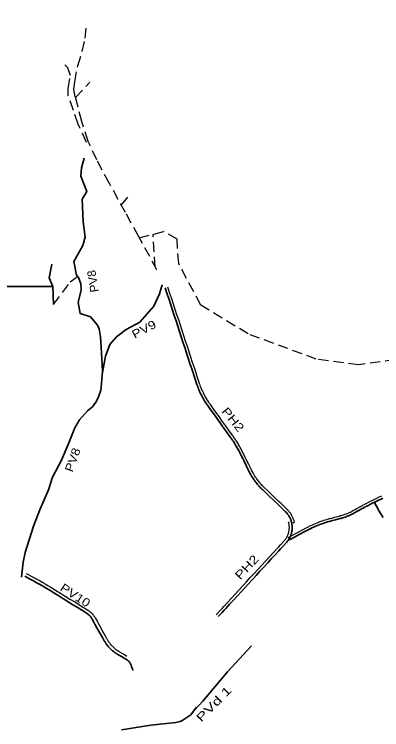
# Model space of a CAD drawing. Extents: x -509392 to -507242, y -1124532 to -1120864.
# Drawn here: x -508657 to -508000, y -1123245 to -1121966 of the extents above; entities that cross this region are included whole.
import ezdxf
from ezdxf.enums import TextEntityAlignment as Align

# ---------------------------------------------------------------- set-up
doc = ezdxf.new("R2010")
doc.units = 0
doc.header["$LTSCALE"] = 6
for name, pattern in [('DOT_DASHED', [7.7, 5, -1.2, 0.3, -1.2]), ('LONG_DASHED', [7.5, 6, -1.5]), ('MEDIUM_DASHED', [4.5, 3, -1.5])]:
    doc.linetypes.add(name, pattern=pattern)
for name, color, linetype, lineweight in [('1', 7, 'DOT_DASHED', 25), ('15', 7, 'Continuous', 35), ('3', 7, 'MEDIUM_DASHED', 25)]:
    doc.layers.add(name, color=color, linetype=linetype, lineweight=lineweight)

msp = doc.modelspace()

# ---------------------------------------------------------------- linework, layer by layer
at = {"layer": '1', "linetype": 'LONG_DASHED'}
msp.add_line((-508477.92, -1123099.313), (-508477.971, -1123099.269), dxfattribs=at)
at = {"layer": '1'}
for points in [[(-508359.897, -1122522.221), (-508363.016, -1122512.72), (-508366.136, -1122503.219), (-508369.255, -1122493.718), (-508372.375, -1122484.217), (-508375.494, -1122474.716), (-508378.614, -1122465.215), (-508381.733, -1122455.714), (-508382.374, -1122453.763)], [(-508251.282, -1122743.872), (-508251.491, -1122743.476), (-508252.955, -1122740.762), (-508254.464, -1122738.065), (-508256.009, -1122735.395), (-508256.289, -1122734.924), (-508257.602, -1122732.739), (-508259.23, -1122730.114), (-508260.896, -1122727.516), (-508261.606, -1122726.434), (-508261.733, -1122726.242), (-508262.607, -1122724.933), (-508264.349, -1122722.389), (-508265.204, -1122721.171), (-508266.132, -1122719.867), (-508267.555, -1122717.886), (-508272.261, -1122711.335), (-508273.389, -1122709.765), (-508276.89, -1122704.892), (-508279.223, -1122701.643), (-508280.39, -1122700.019), (-508281.685, -1122698.216), (-508285.058, -1122693.521), (-508290.892, -1122685.4), (-508296.726, -1122677.278), (-508302.56, -1122669.156), (-508306.271, -1122663.99), (-508307.699, -1122661.967), (-508308.288, -1122661.11), (-508309.079, -1122659.938), (-508310.431, -1122657.876), (-508311.747, -1122655.794), (-508313.029, -1122653.686), (-508313.465, -1122652.95), (-508314.269, -1122651.568), (-508315.478, -1122649.419), (-508316.652, -1122647.249), (-508317.232, -1122646.141), (-508317.784, -1122645.065), (-508318.088, -1122644.463), (-508318.879, -1122642.865), (-508319.939, -1122640.639), (-508320.96, -1122638.398), (-508321.946, -1122636.135), (-508322.135, -1122635.689), (-508322.887, -1122633.868), (-508323.794, -1122631.577), (-508324.66, -1122629.272), (-508325.49, -1122626.945), (-508325.588, -1122626.663), (-508326.278, -1122624.612), (-508328.702, -1122617.231), (-508329.311, -1122615.377), (-508331.821, -1122607.732), (-508331.95, -1122607.337), (-508334.941, -1122598.229), (-508338.061, -1122588.728), (-508341.18, -1122579.227), (-508342.922, -1122573.921), (-508344.299, -1122569.726), (-508347.419, -1122560.225), (-508350.538, -1122550.724), (-508353.658, -1122541.223), (-508356.777, -1122531.722), (-508359.897, -1122522.221)], [(-508158.398, -1122875.663), (-508156.25, -1122874.327), (-508156.894, -1122871.889), (-508156.912, -1122871.822), (-508157.299, -1122870.509), (-508157.744, -1122869.156), (-508158.232, -1122867.817), (-508158.762, -1122866.495), (-508159.333, -1122865.189), (-508159.946, -1122863.903), (-508160.599, -1122862.637), (-508161.23, -1122861.499), (-508161.296, -1122861.383), (-508162.023, -1122860.168), (-508162.794, -1122858.97), (-508163.601, -1122857.796), (-508164.446, -1122856.648), (-508165.326, -1122855.528), (-508166.242, -1122854.436), (-508167.189, -1122853.376), (-508167.989, -1122852.531), (-508168.183, -1122852.332), (-508169.178, -1122851.353), (-508175.342, -1122845.468), (-508178.824, -1122842.143), (-508180.074, -1122840.949), (-508182.574, -1122838.561), (-508189.807, -1122831.655), (-508197.04, -1122824.75), (-508204.272, -1122817.845), (-508209.364, -1122812.982), (-508210.901, -1122811.489), (-508211.389, -1122811.002), (-508212.391, -1122809.984), (-508213.862, -1122808.443), (-508215.305, -1122806.875), (-508216.106, -1122805.979), (-508216.711, -1122805.29), (-508217.872, -1122803.935), (-508218.089, -1122803.676), (-508219.445, -1122802.027), (-508220.766, -1122800.359), (-508222.055, -1122798.668), (-508223.316, -1122796.948), (-508223.733, -1122796.366), (-508224.537, -1122795.217), (-508225.732, -1122793.454), (-508226.893, -1122791.672), (-508228.021, -1122789.867), (-508228.953, -1122788.32), (-508229.112, -1122788.05), (-508230.175, -1122786.201), (-508231.201, -1122784.337), (-508232.193, -1122782.456), (-508233.153, -1122780.548), (-508233.493, -1122779.857), (-508234.92, -1122776.955), (-508237.907, -1122770.882), (-508242.32, -1122761.909), (-508244.042, -1122758.408), (-508246.734, -1122752.936), (-508248.68, -1122748.98), (-508250.06, -1122746.227), (-508250.696, -1122744.993), (-508251.277, -1122743.88)], [(-508167.313, -1122901.536), (-508158.485, -1122896.838), (-508149.658, -1122892.14), (-508140.83, -1122887.442), (-508135.151, -1122884.421), (-508132.447, -1122883.007), (-508131.909, -1122882.732), (-508130.431, -1122881.988), (-508129.699, -1122881.624), (-508126.946, -1122880.289), (-508124.172, -1122878.994), (-508122.677, -1122878.317), (-508121.369, -1122877.737), (-508118.559, -1122876.525), (-508115.727, -1122875.355), (-508113.237, -1122874.367), (-508112.867, -1122874.225), (-508110.009, -1122873.142), (-508107.127, -1122872.101), (-508104.234, -1122871.104), (-508103.601, -1122870.892), (-508101.315, -1122870.146), (-508098.39, -1122869.236), (-508095.454, -1122868.369), (-508093.815, -1122867.906), (-508092.495, -1122867.544), (-508089.541, -1122866.768), (-508084.038, -1122865.365), (-508083.723, -1122865.284), (-508075.915, -1122863.295), (-508075.003, -1122863.063), (-508074.382, -1122862.902), (-508073.045, -1122862.541), (-508072.547, -1122862.402), (-508071.115, -1122861.983), (-508069.186, -1122861.381), (-508067.273, -1122860.74), (-508065.369, -1122860.056), (-508065.312, -1122860.034), (-508063.491, -1122859.336), (-508061.623, -1122858.574), (-508059.772, -1122857.773), (-508057.935, -1122856.931), (-508056.548, -1122856.265), (-508056.129, -1122856.058), (-508054.324, -1122855.136), (-508052.538, -1122854.176), (-508047.942, -1122851.643), (-508044.665, -1122849.837), (-508039.185, -1122846.818), (-508037.43, -1122845.85), (-508035.377, -1122844.718), (-508033.169, -1122843.508), (-508031.069, -1122842.372), (-508030.361, -1122841.991), (-508026.732, -1122840.064), (-508022.38, -1122837.801), (-508021.419, -1122837.308), (-508017.997, -1122835.577), (-508013.602, -1122833.399), (-508012.384, -1122832.805), (-508009.177, -1122831.26), (-508004.74, -1122829.169), (-508003.261, -1122828.484), (-508000.281, -1122827.12)], [(-508295.881, -1123039.702), (-508289.116, -1123032.338), (-508285.549, -1123028.455), (-508282.35, -1123024.974), (-508275.585, -1123017.61), (-508268.82, -1123010.246), (-508262.054, -1123002.882), (-508261.562, -1123002.346), (-508255.289, -1122995.518), (-508248.524, -1122988.153), (-508241.758, -1122980.789), (-508234.993, -1122973.425), (-508228.228, -1122966.061), (-508221.462, -1122958.697), (-508214.697, -1122951.333), (-508207.932, -1122943.969), (-508207.546, -1122943.549), (-508201.166, -1122936.605), (-508194.401, -1122929.241), (-508187.636, -1122921.877), (-508184.672, -1122918.651), (-508180.87, -1122914.512), (-508174.496, -1122907.574), (-508174.157, -1122907.199), (-508173.757, -1122906.745), (-508173.044, -1122905.889), (-508172.36, -1122905.015), (-508171.705, -1122904.121), (-508171.079, -1122903.208), (-508170.482, -1122902.275), (-508169.916, -1122901.322), (-508169.373, -1122900.342), (-508169.203, -1122900.019), (-508168.875, -1122899.372), (-508168.398, -1122898.365), (-508167.956, -1122897.349), (-508167.546, -1122896.319), (-508167.169, -1122895.277), (-508166.825, -1122894.223), (-508166.514, -1122893.156), (-508166.291, -1122892.304), (-508166.239, -1122892.087), (-508166.179, -1122891.834), (-508165.996, -1122891.008), (-508165.787, -1122889.917), (-508165.614, -1122888.822), (-508165.475, -1122887.723), (-508165.371, -1122886.619), (-508165.302, -1122885.513), (-508165.268, -1122884.406), (-508165.27, -1122883.285), (-508165.272, -1122883.158), (-508165.306, -1122882.192), (-508165.377, -1122881.084), (-508165.484, -1122879.981), (-508165.625, -1122878.881), (-508165.801, -1122877.787), (-508166.011, -1122876.699), (-508166.495, -1122874.562), (-508165.43, -1122873.409)]]:
    msp.add_lwpolyline(points, dxfattribs=at)
at = {"layer": '1', "linetype": 'LONG_DASHED'}
for points in [[(-508635.377, -1122965.893), (-508630.727, -1122968.384), (-508626.563, -1122970.615), (-508619.653, -1122974.316), (-508617.719, -1122975.358), (-508615.073, -1122976.801), (-508610.532, -1122979.324), (-508608.835, -1122980.282), (-508605.993, -1122981.908), (-508601.503, -1122984.524), (-508600.053, -1122985.383), (-508597.02, -1122987.199), (-508592.588, -1122989.907), (-508591.397, -1122990.642), (-508582.889, -1122995.897), (-508574.382, -1123001.153), (-508566.96, -1123005.738), (-508565.874, -1123006.409), (-508557.367, -1123011.664), (-508548.859, -1123016.92), (-508540.352, -1123022.176), (-508534.073, -1123026.055), (-508531.844, -1123027.431), (-508525.525, -1123031.335), (-508524.403, -1123032.058), (-508523.3, -1123032.826), (-508522.835, -1123033.166), (-508522.155, -1123033.686), (-508521.1, -1123034.541), (-508520.06, -1123035.449), (-508519.053, -1123036.395), (-508518.085, -1123037.375), (-508517.152, -1123038.388), (-508516.255, -1123039.439), (-508515.399, -1123040.52), (-508514.595, -1123041.613), (-508514.18, -1123042.212), (-508513.807, -1123042.771), (-508513.428, -1123043.363), (-508513.061, -1123043.961), (-508512.405, -1123045.094), (-508508.859, -1123051.496), (-508507.537, -1123053.882), (-508504.013, -1123060.243), (-508499.168, -1123068.991), (-508496.673, -1123073.494), (-508494.322, -1123077.739), (-508491.843, -1123082.214), (-508491.075, -1123083.561), (-508490.289, -1123084.866), (-508489.598, -1123085.955), (-508489.49, -1123086.121), (-508488.628, -1123087.406), (-508487.751, -1123088.646), (-508486.845, -1123089.863), (-508485.907, -1123091.059), (-508484.935, -1123092.24), (-508484.247, -1123093.041), (-508483.962, -1123093.365), (-508482.925, -1123094.505), (-508481.876, -1123095.605), (-508480.801, -1123096.677), (-508479.7, -1123097.723), (-508478.563, -1123098.752), (-508477.92, -1123099.313)], [(-508477.971, -1123099.269), (-508477.436, -1123099.722), (-508476.247, -1123100.698), (-508475.05, -1123101.631), (-508473.829, -1123102.535), (-508472.586, -1123103.411), (-508471.31, -1123104.264), (-508470.818, -1123104.58), (-508470.05, -1123105.061), (-508468.711, -1123105.864), (-508462.459, -1123109.511), (-508460.096, -1123110.889), (-508459.944, -1123110.978), (-508455.617, -1123113.502)]]:
    msp.add_lwpolyline(points, dxfattribs=at)
at = {"layer": '15'}
for points in [[(-508644.106, -1122972.658), (-508640.835, -1122945.778), (-508637.096, -1122928.715), (-508622.141, -1122881.267), (-508610.968, -1122852.189), (-508595.78, -1122816.661), (-508588.303, -1122793.989), (-508572.194, -1122763.217), (-508560.276, -1122735.403), (-508548.827, -1122705.718), (-508540.489, -1122691.347), (-508525.768, -1122674.985), (-508517.122, -1122667.739), (-508511.047, -1122659.792), (-508506.607, -1122651.612), (-508502.168, -1122638.055), (-508500.766, -1122626.368), (-508499.13, -1122604.397), (-508500.999, -1122570.973), (-508502.629, -1122543.053), (-508504.966, -1122528.795), (-508507.77, -1122521.783), (-508520.621, -1122507.057), (-508538.847, -1122501.214), (-508542.352, -1122481.58), (-508537.212, -1122458.908), (-508537.933, -1122448.126), (-508542.139, -1122436.673), (-508545.878, -1122432.7), (-508550.084, -1122408.391), (-508534.194, -1122379.408), (-508529.988, -1122364.682), (-508533.493, -1122337.102), (-508535.363, -1122296.665), (-508527.418, -1122283.109), (-508537.694, -1122255.384), (-508536.76, -1122240.892), (-508531.619, -1122223.595)], [(-508587.609, -1122452.584), (-508594.619, -1122437.158), (-508589.946, -1122412.849)], [(-508498.964, -1122606.363), (-508494.047, -1122577.695), (-508486.116, -1122556.334), (-508473.913, -1122542.907), (-508456.829, -1122529.479), (-508432.423, -1122516.663), (-508407.407, -1122487.977), (-508397.034, -1122466.006), (-508392.763, -1122450.137)], [(-508881.094, -1122652.194), (-508753.512, -1122591.89), (-508733.417, -1122575.061), (-508718.462, -1122558.7), (-508708.648, -1122541.871), (-508680.141, -1122453.052), (-508587.609, -1122452.584), (-508586.674, -1122485.307)], [(-508383.364, -1122466.775), (-508386.484, -1122457.274), (-508387.124, -1122455.323)], [(-508261.87, -1122735.343), (-508263.459, -1122732.781), (-508265.087, -1122730.243), (-508265.777, -1122729.19), (-508265.899, -1122729.007), (-508266.752, -1122727.73), (-508268.455, -1122725.242), (-508269.287, -1122724.056), (-508270.196, -1122722.78), (-508271.615, -1122720.804), (-508276.322, -1122714.252), (-508277.45, -1122712.682), (-508280.95, -1122707.809), (-508283.284, -1122704.56), (-508284.451, -1122702.936), (-508285.746, -1122701.133), (-508289.118, -1122696.439), (-508294.952, -1122688.317), (-508300.787, -1122680.195), (-508306.621, -1122672.074), (-508310.337, -1122666.9), (-508311.806, -1122664.819), (-508312.419, -1122663.927), (-508313.239, -1122662.713), (-508314.636, -1122660.583), (-508315.996, -1122658.429), (-508317.32, -1122656.253), (-508317.776, -1122655.484), (-508318.607, -1122654.054), (-508319.856, -1122651.834), (-508321.068, -1122649.593), (-508321.671, -1122648.443), (-508322.241, -1122647.332), (-508322.558, -1122646.704), (-508323.375, -1122645.051), (-508324.471, -1122642.751), (-508325.527, -1122640.433), (-508326.544, -1122638.098), (-508326.745, -1122637.625), (-508327.522, -1122635.745), (-508328.459, -1122633.376), (-508329.355, -1122630.992), (-508330.211, -1122628.593), (-508330.317, -1122628.287), (-508331.026, -1122626.179), (-508333.452, -1122618.791), (-508334.061, -1122616.936), (-508336.572, -1122609.29), (-508336.702, -1122608.895), (-508339.691, -1122599.789), (-508342.811, -1122590.288), (-508345.93, -1122580.787), (-508347.672, -1122575.481), (-508349.05, -1122571.286), (-508352.169, -1122561.785), (-508355.289, -1122552.284), (-508358.408, -1122542.783), (-508361.528, -1122533.282), (-508364.647, -1122523.781), (-508367.767, -1122514.28), (-508370.886, -1122504.779), (-508374.006, -1122495.278), (-508377.125, -1122485.777), (-508380.245, -1122476.276), (-508383.364, -1122466.775)], [(-508162.902, -1122869.603), (-508163.373, -1122868.427), (-508163.881, -1122867.267), (-508164.426, -1122866.124), (-508165.006, -1122864.998), (-508165.575, -1122863.972), (-508165.622, -1122863.891), (-508166.273, -1122862.804), (-508166.957, -1122861.739), (-508167.675, -1122860.695), (-508168.426, -1122859.675), (-508169.208, -1122858.679), (-508170.022, -1122857.709), (-508170.866, -1122856.765), (-508171.581, -1122856.009), (-508171.739, -1122855.847), (-508172.642, -1122854.958), (-508178.794, -1122849.084), (-508182.277, -1122845.759), (-508183.527, -1122844.565), (-508186.027, -1122842.178), (-508193.26, -1122835.272), (-508200.492, -1122828.367), (-508207.725, -1122821.461), (-508212.824, -1122816.592), (-508214.415, -1122815.045), (-508214.932, -1122814.529), (-508215.977, -1122813.468), (-508217.51, -1122811.863), (-508219.013, -1122810.23), (-508219.85, -1122809.292), (-508220.485, -1122808.569), (-508221.69, -1122807.162), (-508221.926, -1122806.881), (-508223.336, -1122805.167), (-508224.714, -1122803.427), (-508226.059, -1122801.662), (-508227.372, -1122799.872), (-508227.811, -1122799.258), (-508228.651, -1122798.059), (-508229.897, -1122796.222), (-508231.108, -1122794.362), (-508232.285, -1122792.48), (-508233.253, -1122790.872), (-508233.426, -1122790.577), (-508234.533, -1122788.653), (-508235.603, -1122786.709), (-508236.638, -1122784.745), (-508237.635, -1122782.763), (-508237.98, -1122782.063), (-508239.407, -1122779.162), (-508242.394, -1122773.089), (-508246.807, -1122764.116), (-508248.529, -1122760.615), (-508251.221, -1122755.143), (-508253.163, -1122751.193), (-508254.514, -1122748.498), (-508255.133, -1122747.296), (-508255.704, -1122746.205), (-508255.906, -1122745.823), (-508257.338, -1122743.17), (-508258.809, -1122740.538), (-508260.32, -1122737.929), (-508260.586, -1122737.479), (-508261.87, -1122735.343)], [(-508165.081, -1122905.729), (-508156.254, -1122901.032), (-508147.426, -1122896.334), (-508138.598, -1122891.636), (-508132.926, -1122888.618), (-508130.273, -1122887.231), (-508129.755, -1122886.966), (-508128.308, -1122886.236), (-508127.599, -1122885.884), (-508124.906, -1122884.578), (-508122.193, -1122883.312), (-508120.735, -1122882.652), (-508119.461, -1122882.086), (-508116.712, -1122880.902), (-508113.945, -1122879.759), (-508111.511, -1122878.793), (-508111.161, -1122878.657), (-508108.361, -1122877.598), (-508105.545, -1122876.58), (-508102.715, -1122875.605), (-508102.105, -1122875.4), (-508099.87, -1122874.672), (-508097.012, -1122873.781), (-508094.14, -1122872.934), (-508092.541, -1122872.482), (-508091.257, -1122872.13), (-508088.361, -1122871.369), (-508082.863, -1122869.967), (-508082.548, -1122869.887), (-508074.743, -1122867.898), (-508073.826, -1122867.664), (-508073.173, -1122867.496), (-508071.78, -1122867.12), (-508071.247, -1122866.97), (-508069.745, -1122866.532), (-508067.723, -1122865.901), (-508065.715, -1122865.227), (-508063.722, -1122864.511), (-508063.643, -1122864.482), (-508061.744, -1122863.753), (-508059.783, -1122862.953), (-508057.839, -1122862.112), (-508055.913, -1122861.23), (-508054.46, -1122860.531), (-508054.007, -1122860.307), (-508052.12, -1122859.344), (-508050.255, -1122858.342), (-508045.65, -1122855.804), (-508042.373, -1122853.998), (-508036.892, -1122850.977), (-508035.137, -1122850.01), (-508033.086, -1122848.88), (-508030.897, -1122847.68), (-508028.815, -1122846.553), (-508028.118, -1122846.178), (-508024.522, -1122844.268), (-508020.206, -1122842.024), (-508019.26, -1122841.539), (-508015.869, -1122839.823), (-508011.511, -1122837.664), (-508010.31, -1122837.078), (-508007.132, -1122835.548), (-508002.733, -1122833.474), (-508001.273, -1122832.797), (-507998.313, -1122831.443)], [(-508012.886, -1122839.917), (-508007.889, -1122848.579), (-508006.27, -1122851.385), (-508002.892, -1122857.242), (-507997.895, -1122865.904)], [(-508292.199, -1123043.085), (-508285.434, -1123035.721), (-508281.866, -1123031.838), (-508278.668, -1123028.357), (-508271.903, -1123020.992), (-508265.137, -1123013.628), (-508258.372, -1123006.264), (-508257.88, -1123005.729), (-508251.607, -1122998.9), (-508244.841, -1122991.536), (-508238.076, -1122984.172), (-508231.311, -1122976.808), (-508224.545, -1122969.444), (-508217.78, -1122962.08), (-508211.015, -1122954.716), (-508204.249, -1122947.351), (-508203.864, -1122946.932), (-508197.484, -1122939.987), (-508190.719, -1122932.623), (-508183.953, -1122925.259), (-508180.99, -1122922.033), (-508177.188, -1122917.895), (-508170.808, -1122910.95), (-508170.426, -1122910.528), (-508169.966, -1122910.004), (-508169.154, -1122909.032), (-508168.374, -1122908.034), (-508167.625, -1122907.013), (-508166.91, -1122905.968), (-508166.227, -1122904.901), (-508165.579, -1122903.813), (-508164.966, -1122902.704), (-508164.763, -1122902.318), (-508164.388, -1122901.578), (-508163.846, -1122900.433), (-508163.34, -1122899.272), (-508162.872, -1122898.095), (-508162.441, -1122896.904), (-508162.048, -1122895.7), (-508161.693, -1122894.484), (-508161.44, -1122893.515), (-508161.377, -1122893.258), (-508161.307, -1122892.962), (-508161.1, -1122892.022), (-508160.862, -1122890.778), (-508160.664, -1122889.527), (-508160.505, -1122888.27), (-508160.386, -1122887.009), (-508160.307, -1122885.745), (-508160.269, -1122884.479), (-508160.27, -1122883.213), (-508160.273, -1122883.041), (-508160.312, -1122881.947), (-508160.393, -1122880.683), (-508160.515, -1122879.422), (-508160.676, -1122878.166), (-508160.877, -1122876.916), (-508161.117, -1122875.672), (-508161.397, -1122874.437), (-508161.47, -1122874.14), (-508161.716, -1122873.211), (-508161.726, -1122873.174), (-508162.073, -1122871.996), (-508162.469, -1122870.793), (-508162.902, -1122869.603)], [(-508638.096, -1122970.912), (-508633.445, -1122973.403), (-508629.281, -1122975.634), (-508622.373, -1122979.334), (-508620.46, -1122980.366), (-508617.847, -1122981.79), (-508613.349, -1122984.289), (-508611.679, -1122985.233), (-508608.868, -1122986.84), (-508604.423, -1122989.431), (-508602.996, -1122990.276), (-508599.996, -1122992.073), (-508595.606, -1122994.753), (-508594.422, -1122995.485), (-508585.915, -1123000.741), (-508577.407, -1123005.996), (-508569.985, -1123010.581), (-508568.9, -1123011.251), (-508560.392, -1123016.508), (-508551.885, -1123021.763), (-508543.377, -1123027.018), (-508537.098, -1123030.898), (-508534.87, -1123032.275), (-508528.574, -1123036.163), (-508527.606, -1123036.786), (-508526.656, -1123037.447), (-508526.277, -1123037.726), (-508525.708, -1123038.161), (-508524.804, -1123038.892), (-508523.924, -1123039.662), (-508523.072, -1123040.462), (-508522.25, -1123041.293), (-508521.458, -1123042.154), (-508520.698, -1123043.044), (-508519.972, -1123043.96), (-508519.285, -1123044.896), (-508518.94, -1123045.394), (-508518.622, -1123045.869), (-508518.302, -1123046.371), (-508517.996, -1123046.867), (-508517.425, -1123047.856), (-508513.893, -1123054.233), (-508512.571, -1123056.619), (-508509.046, -1123062.981), (-508504.201, -1123071.729), (-508501.706, -1123076.231), (-508499.355, -1123080.476), (-508496.866, -1123084.968), (-508496.039, -1123086.42), (-508495.18, -1123087.844), (-508494.432, -1123089.026), (-508494.298, -1123089.232), (-508493.366, -1123090.619), (-508492.407, -1123091.974), (-508491.417, -1123093.305), (-508490.392, -1123094.612), (-508489.336, -1123095.896), (-508488.585, -1123096.769), (-508488.258, -1123097.141), (-508487.137, -1123098.376), (-508485.99, -1123099.575), (-508484.816, -1123100.748), (-508483.612, -1123101.891), (-508482.379, -1123103.008), (-508481.688, -1123103.609)], [(-508481.704, -1123103.595), (-508481.129, -1123104.084), (-508479.841, -1123105.14), (-508478.533, -1123106.16), (-508477.199, -1123107.148), (-508475.843, -1123108.104), (-508474.456, -1123109.03), (-508473.905, -1123109.385), (-508473.065, -1123109.911), (-508471.627, -1123110.774), (-508465.358, -1123114.429), (-508463, -1123115.805), (-508462.849, -1123115.893), (-508457.071, -1123119.263), (-508456.685, -1123119.493), (-508456.229, -1123119.78), (-508455.42, -1123120.329), (-508454.627, -1123120.919), (-508453.862, -1123121.544), (-508453.126, -1123122.203), (-508452.421, -1123122.894), (-508451.746, -1123123.616), (-508451.106, -1123124.369), (-508450.499, -1123125.148), (-508449.927, -1123125.956), (-508449.399, -1123126.779), (-508449.098, -1123127.287), (-508448.892, -1123127.651), (-508448.44, -1123128.516), (-508448.023, -1123129.411), (-508447.645, -1123130.325), (-508447.31, -1123131.254), (-508447.023, -1123132.176), (-508445.598, -1123137.144), (-508444.937, -1123139.452)], [(-508334.969, -1123210.091), (-508320.05, -1123194.394), (-508275.838, -1123141.819), (-508233.098, -1123095.474)], [(-508465.279, -1123245.262), (-508412.852, -1123237.338), (-508368.114, -1123232.443), (-508360.425, -1123230.812), (-508355.299, -1123228.015), (-508341.455, -1123218.597), (-508330.969, -1123204.846)]]:
    msp.add_lwpolyline(points, dxfattribs=at)
at = {"layer": '3'}
for p, q in [((-508547.466, -1122114.8), (-508521.536, -1122087.496)), ((-508465.335, -1122307.087), (-508449.777, -1122288.247)), ((-508433.423, -1122365.995), (-508389.751, -1122354.254)), ((-508404.765, -1122417.817), (-508408.859, -1122359.659))]:
    msp.add_line(p, q, dxfattribs=at)
for points in [[(-507286.361, -1121962.404), (-507268.347, -1122015.595), (-507263.03, -1122133.19), (-507241.929, -1122192.653), (-507282.455, -1122247.442), (-507365.39, -1122293.005), (-507440.451, -1122315.723), (-507533.877, -1122321.034), (-507578.697, -1122333.173), (-507659.214, -1122380.969), (-507753.404, -1122456.078), (-507783.433, -1122468.728), (-507794.067, -1122491.488), (-507820.653, -1122518.8), (-507875.139, -1122537.55), (-507976.136, -1122583.478), (-508041.695, -1122593.151), (-508117.175, -1122582.596), (-508239.141, -1122537.589), (-508323.505, -1122486.177), (-508363.004, -1122411.827), (-508365.999, -1122368.448), (-508389.751, -1122354.254)], [(-508401.778, -1122423.199), (-508434.532, -1122363.13), (-508458.005, -1122320.809), (-508486.885, -1122268.52), (-508509.518, -1122226.643), (-508524.803, -1122193.605), (-508535.994, -1122158.11), (-508547.731, -1122113.605), (-508550.187, -1122100.226), (-508548.823, -1122086.847), (-508543.097, -1122058.233), (-508535.455, -1122032.568), (-508529.997, -1122008.588), (-508528.36, -1121990.294)], [(-508527.509, -1122195.166), (-508542.522, -1122162.401), (-508550.71, -1122138.101), (-508560.246, -1122111.158), (-508560.519, -1122098.598), (-508556.423, -1122075.698), (-508561.317, -1122061.818), (-508566.503, -1122056.358)], [(-508586.674, -1122485.307), (-508556.619, -1122444.687), (-508543.927, -1122434.67)]]:
    msp.add_lwpolyline(points, dxfattribs=at)

# ---------------------------------------------------------------- texts
at = {"layer": '1'}
for s, rotation, width, p in [('PV8', 99.14, 1.05, (-508508.895, -1122442.281)), ('PV9', 27.57, 1.2, (-508421.554, -1122535.948)), ('PH2', 309.281, 1.25, (-508271.842, -1122695.383)), ('PV8', 70.077, 1.15, (-508545.448, -1122765.344)), ('PH2', 46.857, 1.3, (-508235.913, -1122959.743)), ('PV10', 326.857, 1.2, (-508551.762, -1123011.293)), ('PVd 1', 45.419, 1.45, (-508294.906, -1123204.613))]:
    msp.add_text(s, height=15, rotation=rotation, dxfattribs=dict(at, width=width)).set_placement(p, align=Align.CENTER)

doc.saveas('drawing.dxf')
